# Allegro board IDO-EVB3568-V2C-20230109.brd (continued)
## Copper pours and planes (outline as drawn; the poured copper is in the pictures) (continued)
VDD_3V3 on BOTTOM: 124.66,23.57 124.18,24.05 124.18,24.89 124.59,25.3 126.34,25.3 126.34,28.6 125.12,29.82 125.12,34.42 123.62,35.92 123.62,35.97 121.26,35.97 113.79,28.5 112.57,28.5 111.93,29.15 110.03,29.15 109.45,29.73 99.75,29.73 98.4,31.08 98.4,32.23 100.3,32.23 100.43,32.11 100.43,31.34 100.97,30.81 113.13,30.81 119.63,37.31 123.77,37.31 124.21,37.74 127.48,37.74 128.4,36.83 128.4,24.36 127.61,23.57
VDD_3V3 on BOTTOM: 16.97,45.42 16.97,48.21 17.22,48.46 18.62,48.46 18.77,48.62 22.33,48.62 22.4,48.54 22.4,47.88 22.23,47.7 19,47.7 18.87,47.57 18.87,46.43 17.86,45.42 17.86,44.78 17.98,44.65 19.38,44.65 19.51,44.53 19.51,43.89 19.38,43.76 17.35,43.76 16.79,44.32 16.79,45.24
VDD_3V3 on BOTTOM: 12.65,11.89 13.67,11.89 14.05,12.27 14.05,13.28 13.09,14.24 13.09,15.32 10.74,17.67 10.74,23.57 10.36,23.95 7.82,23.95 7.44,23.57 7.44,22.68 8.84,21.29 8.84,15.7
VDD_3V3 on L2-GND: outline of 100 points within 7.21,1.19 97.76,26.62
VDD_3V3 on L3-POW: 96.98,4.37 95.43,2.82 95.43,2.79 94.59,1.96 94.59,1.73 95.15,1.17 97.03,1.17 98.53,2.67 98.53,3.35 99.19,4.01 123.55,4.01 125.65,6.12 125.65,10.44 127.08,11.86 127.08,14.66 129.46,17.04 129.46,17.07 129.84,17.45 129.84,25.17 129.72,25.3 124.76,25.3 124.31,24.84 124.31,24.41 125.15,23.57 125.7,23.57 126.09,23.19 126.09,21.92 126.7,21.31 126.7,19.63 124.1,17.04 124.1,11.86 122.56,10.31 122.56,8.33 121.26,7.04 102.59,7.04 101.47,5.92 101.02,5.92 100.98,5.96 99.28,5.96 97.69,4.37
VDD_3V3 on L3-POW: 7.19,22.2 9.32,22.2 9.78,22.66 9.78,29.29 9.42,29.64 9.42,41.3 11.43,43.31 16.18,43.31 19.15,46.28 19.15,48.51 18.92,48.74 16.97,48.74 15.95,49.76 15.95,52.07 15.68,52.34 15.2,52.34 15.06,52.2 15.06,51.66 15.01,51.61 15.01,48.79 11.96,45.75 9.6,45.75 7.98,44.12 7.98,26.39 7.21,25.63 7.01,25.63 7.01,22.38
(no net) on TOP: 1.02,0.25 0.48,0.48 0.25,1.02 0.25,89 0.48,89.54 1.02,89.76 134.06,89.76 134.6,89.54 134.82,89 134.82,1.02 134.6,0.48 134.06,0.25 ; 91 cut-outs
(no net) on BOTTOM: 1.02,0.25 0.48,0.48 0.25,1.02 0.25,89 0.48,89.54 1.02,89.76 134.06,89.76 134.6,89.54 134.82,89 134.82,1.02 134.6,0.48 134.06,0.25 ; 64 cut-outs
PHY0_REG_OUT on TOP: 36.4,38.18 36.4,36.91 37.03,36.27 37.03,35.76 37.92,34.87 40.08,34.87 40.21,35 40.21,35.64 40.08,35.76 38.56,35.76 37.92,36.4 37.92,37.03 36.65,38.3 36.53,38.3
PHY1_REG_OUT on TOP: 64.47,32.59 64.34,32.46 63.58,32.46 63.32,32.72 63.32,35.26 61.67,36.91 61.67,37.92 61.8,38.05 62.18,38.05 64.47,35.76
N69300963 on TOP: 14.55,72.21 14.81,71.96 14.81,70.56 14.55,70.31 13.28,70.31 12.78,69.8 12.78,63.58 12.52,63.32 11.25,63.32 11,63.58 11,65.58 10.31,66.27 10.31,72.16 10.36,72.21
N69812073 on TOP: 66.9,65.81 66.9,67.41 67.21,67.72 67.74,67.72 67.79,67.77 67.79,68 67.77,68.02 67.13,68.02 66.74,68.41 66.74,69.58 66.5,69.82 64.97,69.82 64.92,69.77 64.92,65.81 64.97,65.76 66.85,65.76
N69812831 on TOP: 14.43,28.91 17.09,28.91 17.83,28.17 18.41,28.17 18.49,28.09 18.49,27.94 18.41,27.86 17.65,27.86 17.55,27.76 16.54,27.76 16.36,27.58 16.36,25.07 16.13,24.84 14.43,24.84 14.3,24.97 14.3,28.78
N69814391 on TOP: 32.33,26.37 32.33,23.57 32.21,23.44 31.52,23.44 31.42,23.55 31.42,25.5 31.06,25.86 29.01,25.86 28.91,25.96 28.91,26.49 29.03,26.62 32.08,26.62
N69853313 on BOTTOM: 19.33,54.41 19.58,54.15 21.87,54.15 22.38,53.64 22.38,53.26 22.25,53.14 18.06,53.14 17.93,53.26 17.93,54.28 18.06,54.41
N69864462 on TOP: 100.81,28.27 101.04,28.04 101.04,25.55 100.94,25.45 100.38,25.45 100.25,25.58 100.25,26.14 99.26,27.13 99.26,27.38 99.14,27.51 98.88,27.51 98.76,27.64 98.76,28.14 98.88,28.27
N69864477 on TOP: 102.82,25.15 102.82,23.83 102.95,23.7 103.33,23.7 103.45,23.83 103.45,27.28 103.05,27.69 102.51,27.69 102.39,27.56 102.39,25.58
N69887528 on BOTTOM: 103.2,50.6 103.15,50.55 101.04,50.55 100.91,50.67 100.91,51.21 101.09,51.38 102.08,51.38 102.29,51.59 102.29,52.86 102.57,53.14 103.07,53.14 103.2,53.01
N69912226 on TOP: 86.31,23.06 88.85,23.06 89.23,22.68 89.23,20.02 89.1,19.89 86.44,19.89 86.18,20.14 86.18,22.94
N69922778 on TOP: 24.74,19.35 27.13,19.35 27.48,19 28.91,19 28.91,17.73 28.78,17.6 23.19,17.6 21.79,19 21.79,20.4 21.92,20.52 23.57,20.52
N69927169 on TOP: 26.24,9.6 26.37,9.47 28.91,9.47 29.03,9.35 29.03,8.33 28.91,8.2 24.33,8.2 24.08,8.46 24.08,9.47 24.21,9.6

Small or netless copper shapes (teardrops, artwork), in the pictures only: 311 on TOP, 53 on BOTTOM

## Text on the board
Ref Des/Silkscreen Bottom: NC | L-VCC | L-D0P | GND | L-D1P | L-D2P | E_D3P | E_E0P | L_D3P | E_D2P | E_VCC | E_D1P | E_AUXP | L-CLKP | EDP | LVDS | 3V3 | E_D0N | E_D1N | E_D2N | E_D3N | L-D1N | L-D2N | L-D0N | L_D3N | E_AUXN | L_CLKN | E_PWM | E_ON | 12V_IN | GND_IN | 5V | J15 | J31 | J27 | PWR-ON | SW2 | ADC2 | DM_1 | UART0_RTS | CAN1_TX | CAN2_TX | PWM_IR | PWRON | ADC0 | I2C_SDA | SPI_CLK | UART4_TX | UART0_TX | SPI_MOSI | UART7_RX | UART5_TX | SIM1 | ADC3 | ADC1 | DP_1 | RESET | SPI_CS | CAN2_RX | I2C_SCL | CAN1_RX | UART0_RX | UART7_TX | UART5_RX | UART4_RX | SPI_MISO | UART0_CTS | MIC | SW1 | VOLP | VOLN | VORP | VORN | RECOVERY | VCC | RST | INT | SCL | SDA | DM3 | DP3 | DM2 | DP2 | DM1 | DP1
Ref Des/Silkscreen Top: J1 | J18 | J22 | J17 | V_RTC | J25 | GND | J23 | MIPI-CSI1 | J20 | J14 | MIPI-CSI0 | J4 | G | T | R | J19 | LED1 | MIPI-DSI-TX1 | J6 | J13 | J3 | J9 | J10 | J8 | J5 | J7 | J11 | J24 | J30 | J16 | J28 | J29 | J12 | IDO-EVB3568-V2C
DEVICE_TYPE_TOP: 2 | 1 | 3 | 6 | 4 | 5 | 32 | 25 | 24 | 17 | 8 | 16 | 9 | +
DISPLAY_BOTTOM: FIGURE | SIZE | 7.874 | 11.811 | 27.559 | 28.0 | 31.496 | 35.0 | 36.0 | 39.37 | 40.0 | 65.0 | 66.929 | 86.614 | 93.0 | 102.362 | 145.669 | 169.291 | 23.622 | 27.992 | 43.311 | 44.016 | 45.0 | 62.988 | 62.992 | 90.551 | 128.0 | 55.118x27.559 | 59.055x23.622 | 70.866x23.622 | 78.74x23.622 | 78.74x31.5 | 94.488x27.559 | DRILL CHART: TOP to BOTTOM | ALL UNITS ARE IN MILS | PLATED | NON-PLATED | QTY | 44 | 1914 | 40 | 18 | 12 | 34 | 20 | 4 | 36 | 8 | 1 | 2 | 3
